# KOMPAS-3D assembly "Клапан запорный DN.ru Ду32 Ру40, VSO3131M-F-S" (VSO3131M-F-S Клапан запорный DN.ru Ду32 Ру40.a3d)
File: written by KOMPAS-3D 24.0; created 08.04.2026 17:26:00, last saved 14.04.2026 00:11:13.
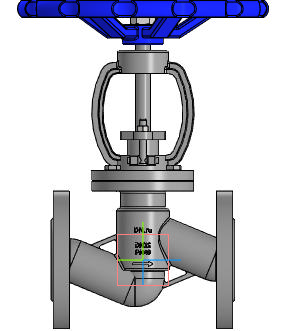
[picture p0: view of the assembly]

Document properties: Автор: R2D2; Полное имя файла: E:\Работа\Зайцев\VSO3131M-F-S Клапан запорный DN.ru Ду15-100 Ру40\DN32\исходные материалы\VSO3131M-F-S Клапан запорный DN.ru Ду32 Ру40.a3d

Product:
- Component [detail]: Корпус  | qty 1  | pos. 1  | Масса: 6.9; Автор: R2D2; source file: Корпус.m3d
- Component [detail]: Клапан запорный DN.ru Ду32 Ру16  | designation VSO1121M-F-S  | qty 1  | pos. 2  | Масса: 7.9; Раздел спецификации: Прочие изделия; Примечание: D090-01945; Автор: R2D2; source file: 2.m3d
- Component [standard]: Hexagon head screw ISO 4017 - М8 x 16  | qty 4  | Масса: 0.012085; Раздел спецификации: Стандартные изделия; Рассекать на разрезах: no
- Part/product: Клапан запорный DN.ru Ду32 Ру40  | designation VSO3131M-F-S
    Масса: 7.04
    Раздел спецификации: Прочие изделия
    Примечание: D090-02140

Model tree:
1. Массив по концентрической сетке:1  (with: Грань.Элемент вращения:2, Грань.Элемент выдавливания:3)  (labels: Грань.Твердое тело1; Грань.Элемент выдавливания:9.Экземпляр ( 1, 2 ))  (4 pattern instances)
     Шаг 2 = 360

Expressions: D090-01945
Referenced files in E:\Работа\Зайцев\VSO3131M-F-S Клапан запорный DN.ru Ду15-100 Ру40\DN32\исходные материалы\: Корпус.m3d, 2.m3d
Referenced files in C:\Program Files\ASCON\KOMPAS-3D v24\Libs\PolynomLib\DATA\vault\Methods\Kompas\3D\: PLib_Bolt_1_ISO_1100.m3d
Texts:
  VSO1121M-F-S
  Hexagon head screw
  BOSimple***PART:17775d1c-e7de-f283-40f0-d40789f7f59e***SHORTLOC:A259_7B16EF33AB1642D2[13;1,25;16;8;-;Undefined]
  Программные изделия  и базы данных
  VSO3131M-F-S
  VSO1121M-F-S Клапан запорный DN.ru Ду32 Ру16
  Hexagon head screw ISO 4017 - М8 x 16 (1)
  hole1
  hole2
  Hexagon head screw ISO 4017 - М8 x 16 (2)
  Hexagon head screw ISO 4017 - М8 x 16 (3)
  Hexagon head screw ISO 4017 - М8 x 16 (4)
  Ось Y.Начало координат
  Плоскость XY.Начало координат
